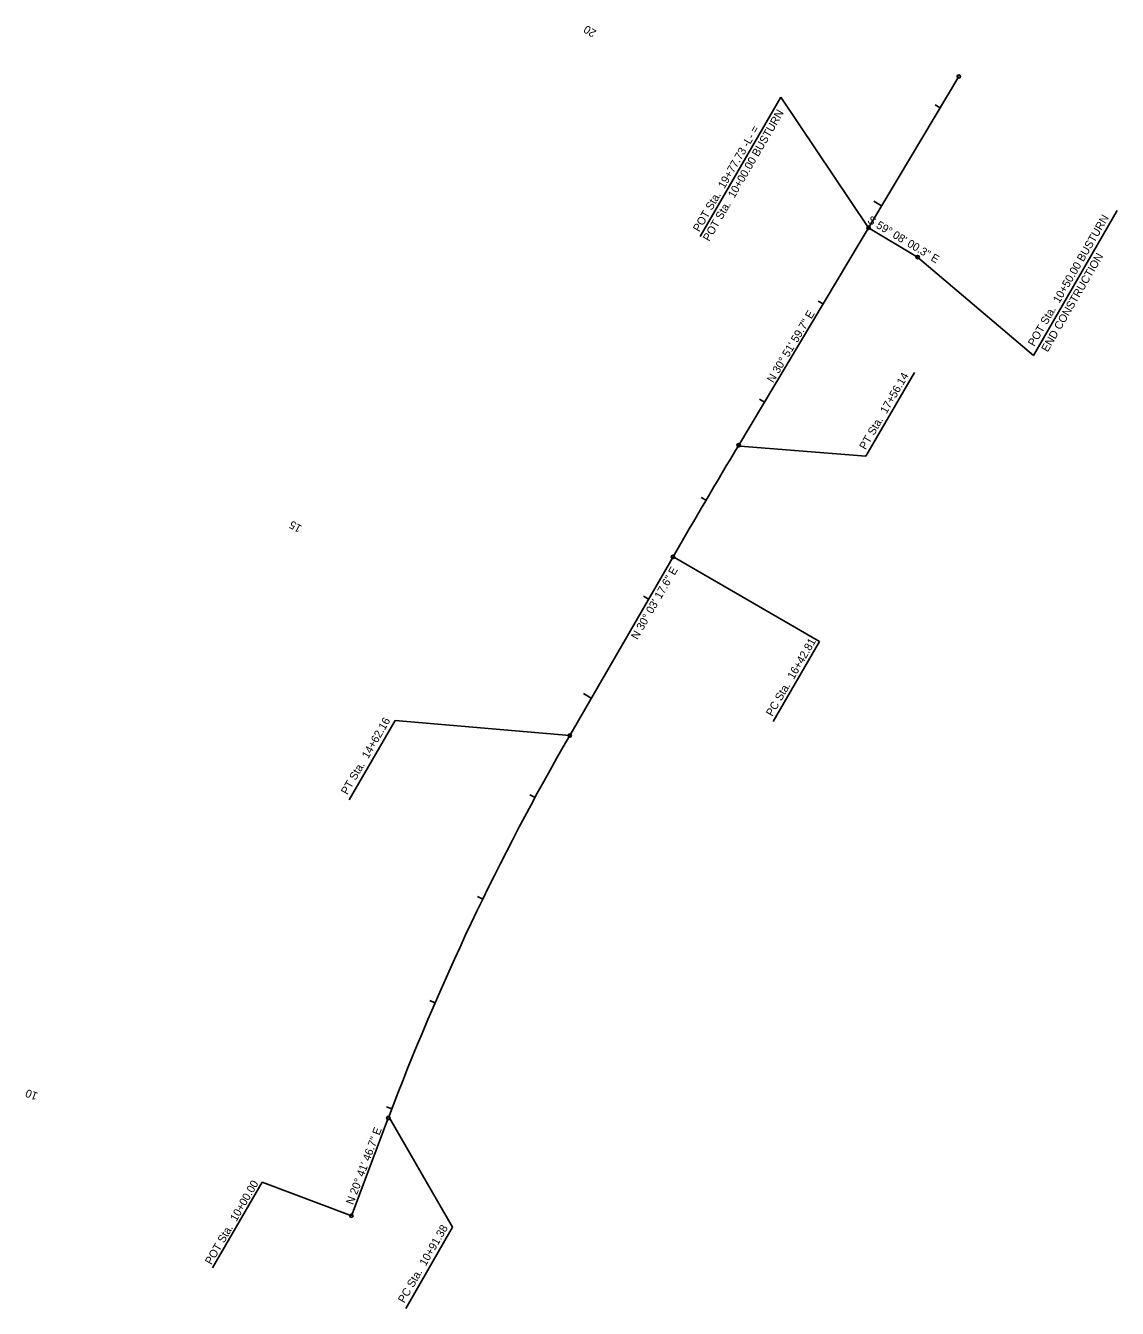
# Model space of a CAD drawing. Extents: x 1653255 to 1654211, y 597487 to 598609.
import ezdxf

# ---------------------------------------------------------------- set-up
doc = ezdxf.new("R2010")
doc.units = 0
for name, color, linetype in [('Exist Roads EOP Cogo Number', 7, 'Continuous'), ('Exist Roads EOT Cogo Number', 7, 'Continuous'), ('Exist Roads EOT Cogo Point CELL', 7, 'Continuous'), ('Exist Structure Major Bridge WW Cogo Point CELL', 7, 'Continuous'), ('Exist Structure Minor Culvert Topo', 7, 'Continuous'), ('Exist Structure Minor Culvert Topo Terminator', 7, 'Continuous')]:
    doc.layers.add(name, color=color, linetype=linetype)

msp = doc.modelspace()

# ---------------------------------------------------------------- linework, layer by layer
at = {"layer": 'Exist Roads EOP Cogo Number'}
for p, q in [((1653845.7, 598424.7), (1653916.3, 598546.5)), ((1653993.2, 598432.3), (1653916.3, 598546.5)), ((1654137.6, 598320.6), (1654210.9, 598447.3)), ((1654036.1, 598406.6), (1654137.6, 598320.6)), ((1653990.8, 598232.3), (1654033.3, 598305.7)), ((1653880.8, 598241.3), (1653990.8, 598232.3)), ((1653823.3, 598143.7), (1653950.1, 598070.3)), ((1653909.6, 598000.2), (1653950.1, 598070.3)), ((1653538.6, 597931.9), (1653578.7, 598001.1)), ((1653731.6, 597988), (1653578.7, 598001.1)), ((1653574.2, 597652.9), (1653629.1, 597557.9)), ((1653419, 597522.4), (1653462.4, 597597.4)), ((1653539.1, 597568.5), (1653462.4, 597597.4)), ((1653588, 597486.9), (1653629.1, 597557.9))]:
    msp.add_line(p, q, dxfattribs=at)
for centre in [(1654072.2, 598564.5), (1653993.2, 598432.3), (1654036.1, 598406.6), (1653879.5, 598242.1), (1653822, 598144.4), (1653731.6, 597988), (1653572.8, 597653.4), (1653540.5, 597567.9)]:
    msp.add_circle(centre, 1.5, dxfattribs=at)
at = {"layer": 'Exist Roads EOT Cogo Number'}
for p, q in [((1654004.6, 598451.4), (1653997.7, 598455.5)), ((1653993.2, 598432.3), (1653997.3, 598439.2)), ((1653750.5, 598020.8), (1653743.6, 598024.8)), ((1653540.5, 597567.9), (1653533.1, 597570.8))]:
    msp.add_line(p, q, dxfattribs=at)
at = {"layer": 'Exist Structure Major Bridge WW Cogo Point CELL'}
for p, q in [((1654055.9, 598537.3), (1654051.6, 598539.8)), ((1653953.3, 598365.6), (1653949, 598368.1)), ((1653902, 598279.7), (1653897.7, 598282.3)), ((1653850.9, 598193.8), (1653846.5, 598196.3)), ((1653800.6, 598107.4), (1653796.3, 598109.9)), ((1653701.2, 597933.8), (1653696.8, 597936.2)), ((1653655.4, 597844.9), (1653650.9, 597847.1)), ((1653613.6, 597754.1), (1653609.1, 597756.1)), ((1653575.9, 597661.5), (1653571.2, 597663.3))]:
    msp.add_line(p, q, dxfattribs=at)
at = {"layer": 'Exist Structure Minor Culvert Topo Terminator'}
for p, q in [((1653879.5, 598242.1), (1654072.2, 598564.5)), ((1653993.2, 598432.3), (1654036.1, 598406.6)), ((1653731.6, 597988), (1653822, 598144.4)), ((1653540.5, 597567.9), (1653572.8, 597653.4))]:
    msp.add_line(p, q, dxfattribs=at)
for centre, radius, start, end in [((1660746.4, 594137.8), 8000, 149.13342, 149.9451), ((1655696.4, 596851.2), 2270, 149.9451, 159.3037)]:
    msp.add_arc(centre, radius, start, end, dxfattribs=at)

# ---------------------------------------------------------------- texts
at = {"layer": 'Exist Roads EOP Cogo Number'}
for s, p in [('POT Sta.  10+00.00 BUSTURN', (1653853.7, 598419.8)), ('POT Sta.  19+77.73 -L- =', (1653845, 598428.1)), ('POT Sta.  10+50.00 BUSTURN', (1654138.2, 598327.9)), ('END CONSTRUCTION', (1654149.9, 598323)), ('PT Sta.  17+56.14', (1653990.6, 598237.5)), ('PC Sta.  16+42.81', (1653908.9, 598004.2)), ('PT Sta.  14+62.16', (1653536.9, 597935.7)), ('POT Sta.  10+00.00', (1653417.9, 597524.5)), ('PC Sta.  10+91.38', (1653586.8, 597491))]:
    msp.add_text(s, height=7, rotation=59.9255, dxfattribs=at).set_placement(p)
at = {"layer": 'Exist Roads EOT Cogo Point CELL'}
for s, rotation, p in [('20', 149.1334, (1653755.4, 598604.4)), ('15', 149.9451, (1653497.7, 598171.1)), ('10', 159.3037, (1653266.6, 597675.2))]:
    msp.add_text(s, height=7, rotation=rotation, dxfattribs=at).set_placement(p)
at = {"layer": 'Exist Structure Minor Culvert Topo'}
for s, rotation, p in [('S 59%%d 08\' 00.3" E', 329.1334, (1653991.6, 598437.2)), ('N 30%%d 51\' 59.7" E', 59.1334, (1653909.7, 598296.1)), ('N 30%%d 03\' 17.6" E', 59.9451, (1653790.8, 598071.4)), ('N 20%%d 41\' 46.7" E', 69.3037, (1653542, 597577))]:
    msp.add_text(s, height=7, rotation=rotation, dxfattribs=at).set_placement(p)

doc.saveas('drawing.dxf')
